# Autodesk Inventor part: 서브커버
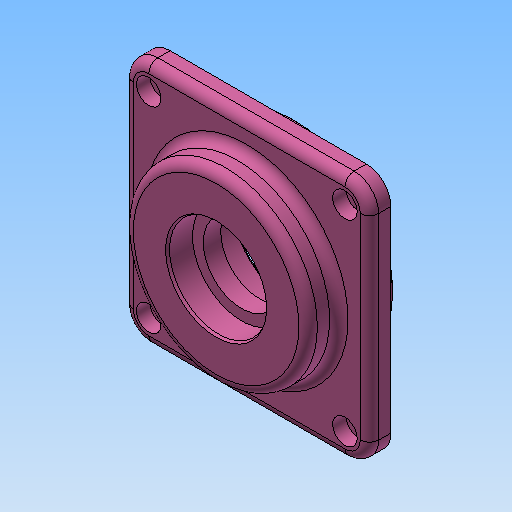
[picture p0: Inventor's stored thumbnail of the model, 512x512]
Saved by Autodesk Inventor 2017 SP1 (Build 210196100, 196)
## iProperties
Created: 2018-09
Part Number: 서브커버
Material: 알루미늄 6061
Document SubType Name: Modeling
Designer: mduedu
Density: 2.71 g/cm^3
Mass: 206.54 g
Surface Area: 196.569 cm^2
Volume: 76.2142 cm^3
Appearance: 분홍색
Author: mduedu
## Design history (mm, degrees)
sketch "스케치1"
  geometry: L1 (-40, -40)-(40, -40); L2 (40, -40)-(40, 40); L3 (40, 40)-(-40, 40); L4 (-40, 40)-(-40, -40); L5 (-40, -40)-(40, 40); L6 (40, -40)-(-40, 40); 1 further point
  constraints: 12 end point, 2 midpoint, 2 parallel, 1 horizontal, 1 perpendicular
  dimensions: "d0" = 80 distance of L3.end L2.end; "d1" = 80 distance of L2.end L1.end
extrude "돌출1" new body sketch "스케치1" distance "d2" = 7; taper "d3" = 0 deg
sketch "스케치2"
  geometry: C1 r 30 at (0, 0); 1 further point
  constraints: 1 centre point, 1 coincident
  dimensions: "d4" = 60 diameter of C1
extrude "돌출2" join sketch "스케치2" distance "d5" = 10; taper "d6" = 0 deg
sketch "스케치3"
  geometry: C1 r 32.5 at (0, 0); 1 further point
  constraints: 1 centre point, 1 coincident
  dimensions: "d7" = 65 diameter of C1
extrude "돌출3" join sketch "스케치3" distance "d8" = 9; taper "d9" = 0 deg
sketch "스케치4"
  geometry: L1 (-32.5, -9)-(32.5, -9) reference; L2 (30, 17)-(-30, 17) reference; L3 (0, 17)-(0, -9); L4 (0, -9)-(20, -9); L5 (20, -9)-(20, 3); L6 (20, 3)-(0, 3); L7 (0, 3)-(0, -9); L8 (0, 3)-(12.5, 3); L9 (12.5, 3)-(12.5, 8.7); L10 (12.5, 8.7)-(0, 8.7); L11 (0, 8.7)-(0, 3); L12 (0, 8.7)-(16, 8.7); L13 (16, 8.7)-(16, 17); L14 (16, 17)-(0, 17); L15 (0, 17)-(0, 8.7); 1 further point
  constraints: 26 end point, 6 parallel, 3 horizontal, 3 perpendicular, 2 midpoint, 1 point on line
  dimensions: "d10" = 12 distance of L4.end L5.end; "d12" = 8.3 distance of L12.end L13.end; "d13" = 32 diameter of L13 L3; "d14" = 25 diameter of L9 L3; "d15" = 40 diameter of L5 L3
revolve "회전1" sketch "스케치4" stored, may be unused: angle "d16" = 90 deg
fillet "모깎기1" dims "d17" = 8
fillet "모깎기2" dims "d18" = 3
fillet "모깎기3" dims "d19" = 3
chamfer "모따기1" distance "d20" = 0.8; stored, may be unused: second distance "d21" = 2, angle "d22" = 30 deg
chamfer "모따기2" distance "d23" = 1; stored, may be unused: second distance "d24" = 2, angle "d25" = 30 deg
fillet "모깎기4" dims "d26" = 0.3
sketch "스케치5"
  geometry: A1 r 8 centre (-32, 32) between (-32, 40) and (-40, 32) reference; A2 r 8 centre (-32, -32) between (-40, -32) and (-32, -40) reference; A3 r 8 centre (32, -32) between (32, -40) and (40, -32) reference; A4 r 8 centre (32, 32) between (40, 32) and (32, 40) reference; 5 further points
  constraints: 4 coincident
hole "구멍1" sketch "스케치5" at (-32, 32), (32, 32), (32, -32), (-32, -32) diameter "d27" = 4.5; stored, may be unused: countersink angle "d31" = 90 deg, drill point angle "d33" = 118 deg; dims "d28" = 6, "d29" = 8, "d30" = 4.4, "d32" = 8
fillet "모깎기5" dims "d34" = 0.5
node "솔리드1"
